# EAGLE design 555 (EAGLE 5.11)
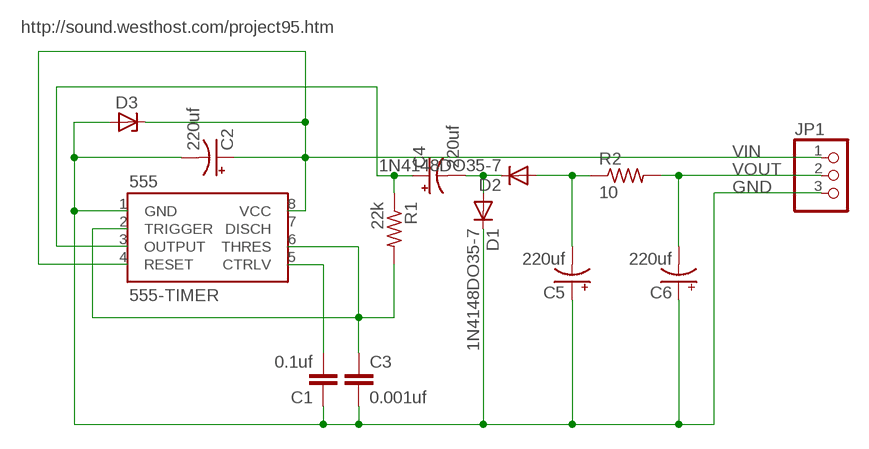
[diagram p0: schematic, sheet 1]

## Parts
555  555-TIMER  [8DIP]
C1  0.1uf  C-EU050-024X044  [C050-024X044]
C2  220uf  CPOL-USE5-8.5  [E5-8,5]
C3  0.001uf  C-EU050-024X044  [C050-024X044]
C4  220uf  CPOL-USE5-8.5  [E5-8,5]
C5  220uf  CPOL-USE5-8.5  [E5-8,5]
C6  220uf  CPOL-USE5-8.5  [E5-8,5]
D1  1N4148DO35-7  [DO35-7]
D2  1N4148DO35-7  [DO35-7]
D3  ZENER-DIODEDO41Z10  [DO41Z10]
JP1  PINHD-1X3  [1X03]
R1  22k  R-US_0309/10  [0309/10]
R2  10  R-US_0309/10  [0309/10]

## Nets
GND: 555.1(GND) C1.1 C2.- C3.2 C5.+ C6.+ D1.C D3.A JP1.3
N$1: C5.- D2.A R2.1
N$2: C4.- D1.A D2.C
N$3: 555.2(TRIGGER) 555.6(THRES) C3.1 R1.2
N$4: 555.3(OUTPUT) C4.+ R1.1
N$6: 555.5(CTRLV) C1.2
VIN: 555.4(RESET) 555.8(VCC) C2.+ D3.C JP1.1
VOUT: C6.- JP1.2 R2.2
Unconnected: 555.7(DISCH)

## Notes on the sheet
- http://sound.westhost.com/project95.htm

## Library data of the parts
555 = trl:555-TIMER
C1 C3 = rcl:C-EU: CAPACITOR, European symbol
C2 C4-C6 = rcl:CPOL-US: POLARIZED CAPACITOR, American symbol
D1 D2 = diode:1N4148: DIODE
D3 = diode:ZENER-DIODE: Z-Diode
JP1 = pinhead:PINHD-1X3: PIN HEADER
R1 R2 = resistor:R-US_: RESISTOR, American symbol

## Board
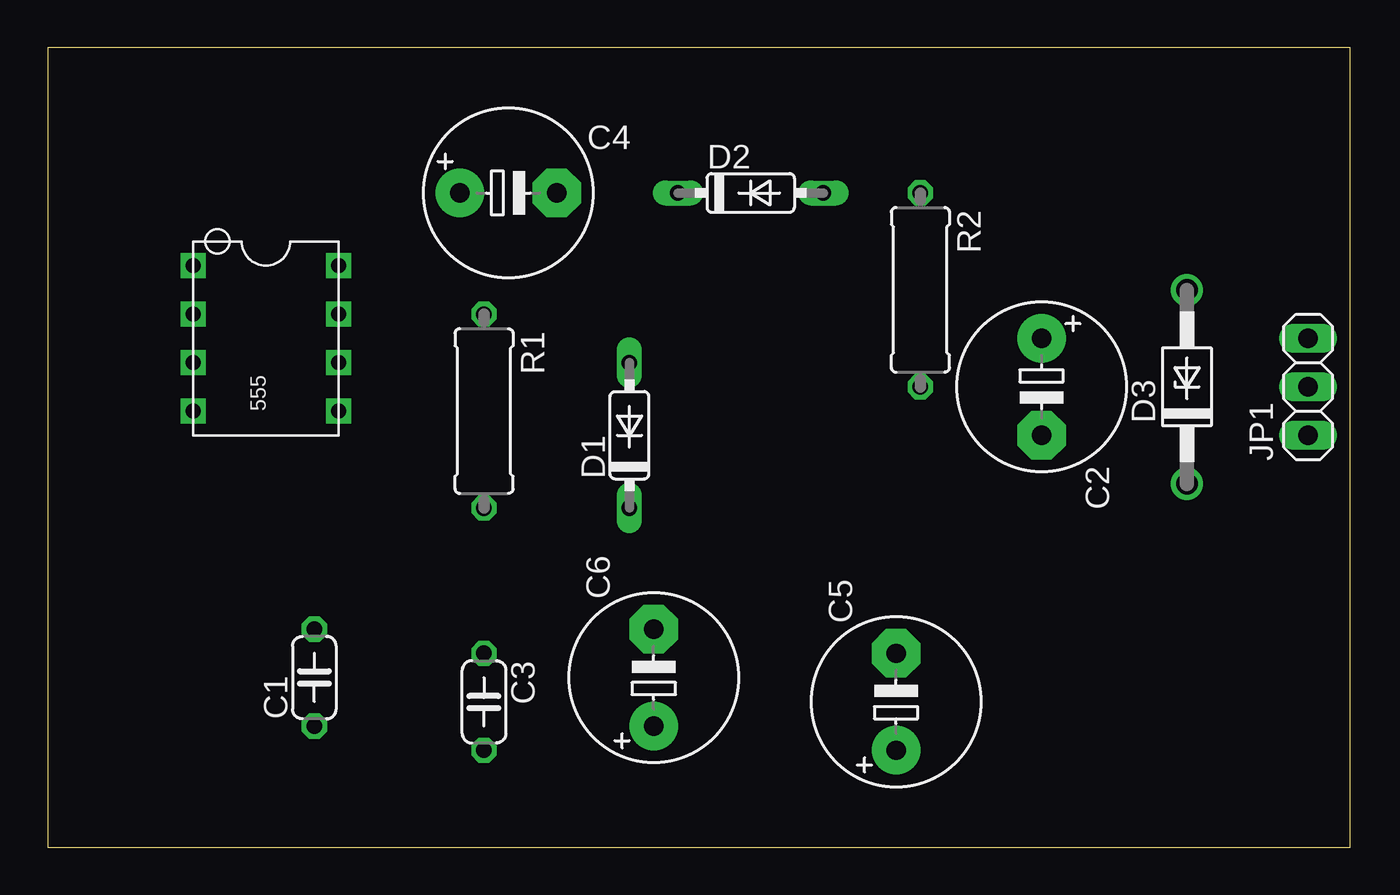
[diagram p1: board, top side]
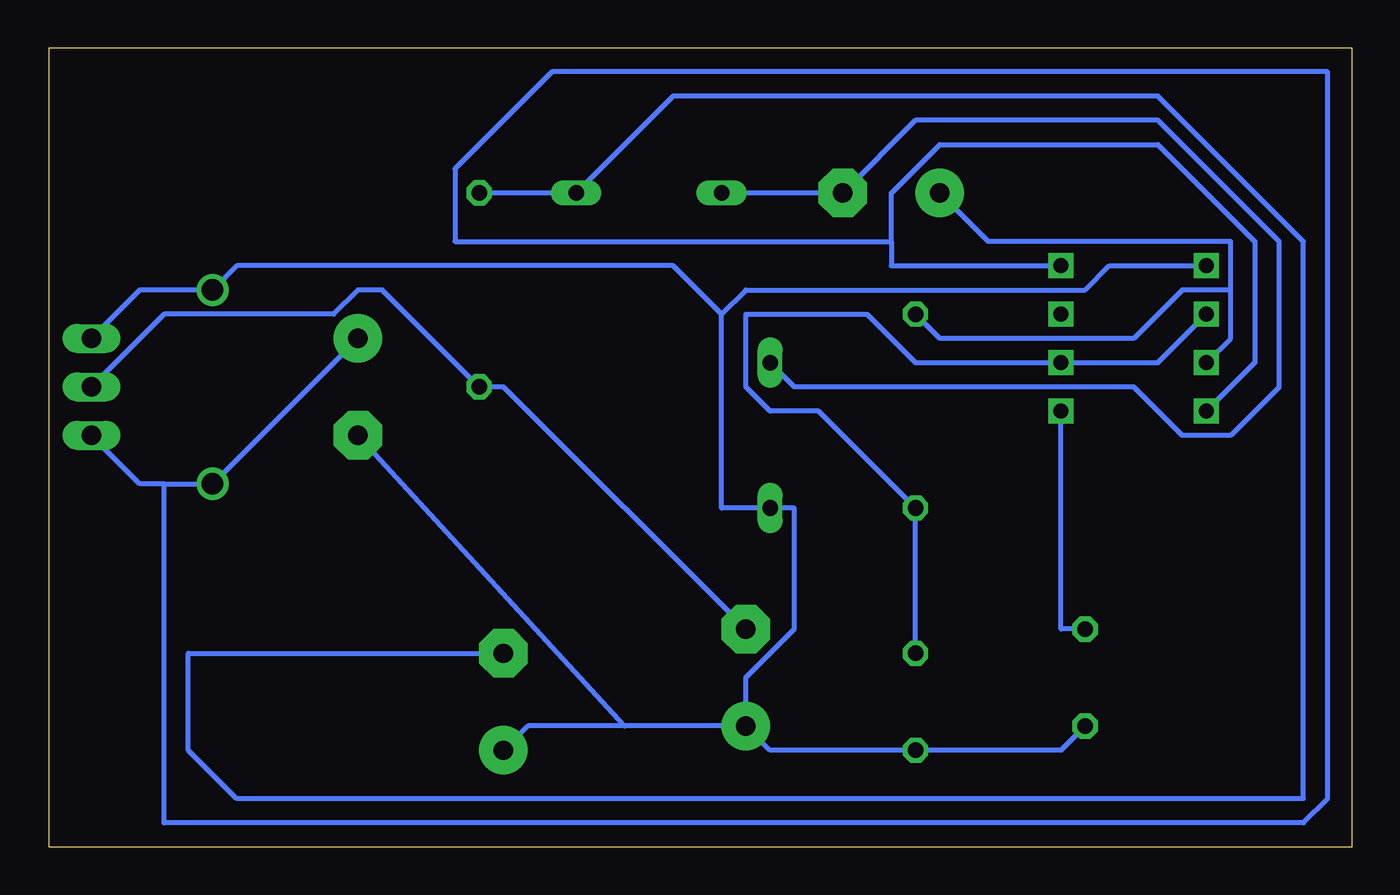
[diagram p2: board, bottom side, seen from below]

Size 68.25 x 41.9 mm. Coordinates in mm from the lower left corner, seen from the top.
Outline: 0,0 68.25,0 68.25,41.9 0,41.9 0,0
Copper layers (1*16): Top 0.035mm / dielectric 1.5mm / Bottom 0.035mm
Design rules "default": minimum track width 10mil, minimum drill 24mil, track to track 8mil, track to pad 8mil, pad to pad 8mil, via to via 8mil, smd to smd 8mil, copper to edge 40mil, drill to drill 8mil, minimum pad ring 10mil, minimum via ring 8mil, stop-mask expansion 4mil, vias tented up to drill 0mil, thermal gap 10mil

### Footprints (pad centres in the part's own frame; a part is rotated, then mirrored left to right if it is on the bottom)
8DIP = drill 0.8 square: 1 -3.81,3.81; 2 -3.81,1.27; 3 -3.81,-1.27; 4 -3.81,-3.81; 5 3.81,-3.81; 6 3.81,-1.27; 7 3.81,1.27; 8 3.81,3.81
C050-024X044 = drill 0.813 octagon: 1 -2.54,0; 2 2.54,0
E5-8,5 = drill 1.016 pad 2.54 round: + -2.54,0 | drill 1.016 pad 2.54 octagon: - 2.54,0
DO35-7 = drill 0.813 long: A 3.81,0; C -3.81,0
DO41Z10 = drill 1.118 round: A 5.08,0; C -5.08,0
1X03 = drill 1.016 long: 1 -2.54,0; 2 0,0; 3 2.54,0
0309/10 = drill 0.813 octagon: 1 -5.08,0; 2 5.08,0

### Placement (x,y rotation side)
555  11.43,26.67 0 top
C1  13.97,8.89 90 top
C2  52.07,24.13 270 top
C3  22.86,7.62 270 top
C4  24.13,34.29 0 top
C5  44.45,7.62 90 top
C6  31.75,8.89 90 top
D1  30.48,21.59 90 top
D2  36.83,34.29 0 top
D3  59.69,24.13 90 top
JP1  66.04,24.13 90 top
R1  22.86,22.86 270 top
R2  45.72,29.21 270 top

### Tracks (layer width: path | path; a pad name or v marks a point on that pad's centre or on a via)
GND
  Bottom 0.254: C1.1 15.24,5.08 C3.2 30.48,5.08 C6.+ | C5.+ 43.18,6.35 38.1,6.35 | C6.+ 38.1,6.35 | C6.+ 31.75,8.89 29.21,11.43 29.21,17.78 D1.C 33.02,17.78 33.02,27.94 | 38.1,6.35 C2.- | JP1.3 63.5,29.21 D3.A 58.42,30.48 35.56,30.48 33.02,27.94 | 555.1 12.7,30.48 13.97,29.21 31.75,29.21 33.02,27.94
N$1
  Bottom 0.254: R2.1 D2.A 35.56,39.37 10.16,39.37 2.54,31.75 2.54,2.54 58.42,2.54 60.96,5.08 60.96,10.16 C5.-
N$2
  Bottom 0.254: D1.A 29.21,24.13 11.43,24.13 8.89,21.59 6.35,21.59 3.81,24.13 3.81,31.75 10.16,38.1 22.86,38.1 C4.- D2.C
N$3
  Bottom 0.254: C3.1 R1.2 27.94,22.86 30.48,22.86 31.75,24.13 31.75,27.94 25.4,27.94 22.86,25.4 555.6 10.16,25.4 555.2
N$4
  Bottom 0.254: 555.3 6.35,26.67 6.35,29.21 | 6.35,29.21 6.35,31.75 19.05,31.75 C4.+ | R1.1 21.59,26.67 11.43,26.67 8.89,29.21 6.35,29.21
N$6
  Bottom 0.254: 555.5 15.24,11.43 C1.2
VIN
  Bottom 0.254: JP1.1 63.5,19.05 62.23,19.05 | 62.23,19.05 D3.C C2.+ | 555.4 5.08,25.4 5.08,31.75 10.16,36.83 21.59,36.83 24.13,34.29 24.13,31.75 | 24.13,31.75 24.13,30.48 555.8 | 62.23,19.05 62.23,1.27 2.54,1.27 1.27,2.54 1.27,40.64 41.91,40.64 46.99,35.56 46.99,31.75 24.13,31.75
VOUT
  Bottom 0.254: C6.- 44.45,24.13 R2.2 50.8,29.21 52.07,29.21 53.34,27.94 62.23,27.94 JP1.2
